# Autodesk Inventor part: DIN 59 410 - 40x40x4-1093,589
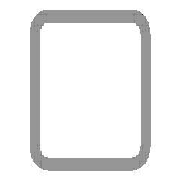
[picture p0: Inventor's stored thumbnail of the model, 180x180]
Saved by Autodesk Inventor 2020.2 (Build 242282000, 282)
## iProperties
Manager: www.cadconsulting.pl
Company: Fabian Stasiak CAD Consulting
IsCustomPart: 1
_CCFamilyMember: 20
_CCFamilyDisplayName: DIN 59410 (Kwadrat) - Rurki stalowe o przekroju kwadratowym formowane na gorąco
_FrameMemberDoc: Frame Member File
_Version: 15.0.0
_GetPNFromCC: 1
Created: 2015-01
Part Number: DIN 59 410 - 40x40x4-1093,589
Material: Stal, miękka
Description: Rurki stalowe o przekroju kwadratowym formowane na gorąco
Document SubType Name: Modellieren
Standard: DIN
Designer: F.Stasiak
Standards Organization: DIN
Language: pl-PL
Size Designation: 40x40x4
Categories: <MemberInstance><Categories><Category DisplayName="Kształtowniki konstrukcyjne" InternalName="089c4875-fa83-4c05-b084-43b9cc11f5ed" Mnemonic="GRDR"><CategoryPar
Stock Number: 40x40x4
Density: 7.85 g/cm^3
Appearance: Częściowo polerowana
Mass: 4423.13 g
Surface Area: 2832.4 cm^2
Volume: 563.456 cm^3
Catalog Web Link: www.expertbooks.pl
G_W: 40,000 mm
G_H: 40,000 mm
+65DF158C-447B-4050-950E-ACB0F4E1A603+CUTDETAIL1: Wytnij
+30AF1056-0509-4B5D-B1E7-E99203BB6F11+CUTDETAIL2: Wytnij
G_L: 1093,589 mm
Author: F.Stasiak
Subject: Zbiór ćwiczeń. Autodesk Inventor 2020. Kurs Professional
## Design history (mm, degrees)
node "Płaszczyzna początkowa"
node "Płaszczyzna końcowa"
sketch "Szkic1"
  geometry: L1 (-12, 20)-(12, 20); L2 (20, 12)-(20, -12); L3 (12, -20)-(-12, -20); L4 (-20, -12)-(-20, 12); L5 (-30.32, 0)-(30.32, 0) reference; L6 (0, -30.32)-(0, 30.32) reference; L7 (-12, 16)-(12, 16); L8 (16, 12)-(16, -12); L9 (12, -16)-(-12, -16); L10 (-16, -12)-(-16, 12); A1 r 8 centre (-12, 12) between (-12, 20) and (-20, 12); A2 r 8 centre (12, 12) between (20, 12) and (12, 20); A3 r 8 centre (12, -12) between (12, -20) and (20, -12); A4 r 8 centre (-12, -12) between (-20, -12) and (-12, -20); A5 r 4 centre (-12, 12) between (-12, 16) and (-16, 12); A6 r 4 centre (12, 12) between (16, 12) and (12, 16); A7 r 4 centre (12, -12) between (12, -16) and (16, -12); A8 r 4 centre (-12, -12) between (-16, -12) and (-12, -16); 3 further points
  constraints: 16 end point, 16 point on circle, 8 centre point, 8 tangent, 6 point on line, 4 parallel, 3 equal radius, 3 perpendicular, 1 horizontal, 7 other
  dimensions: "b" = 40 distance of point (-20, 20) point (20, 20); "msp_r" = 8 radius of A1 (= 2 x ParT); "d8" = 20 distance between parallel lines of L4 L6 (= d9); "d9" = 20 distance between parallel lines of L3 L5 (= 0.5 x b); "d10" = 4 distance between parallel lines of L3 L9 (= ParT)
extrude "Bryła" new body sketch "Szkic1" taper "d4" = 0 deg; stored distance "NLG" = 10
node "Driven Length"
  sketch "Sketch2"
    geometry: L1 (0, 0)-(10, 0) reference
    constraints: 2 end point, 1 horizontal
  workplane "Work Plane3"
  sketch "Sketch3"
    geometry: L1 (-2, 22.426)-(12, 22.426) reference; L2 (-2, 1116.016)-(12, 1116.016) reference
    dimensions: "d14" = 1093.5891 distance between parallel lines of L1 L2 (derived)
node "Płaszczyzna konstrukcyjna4"
feature "Podział1"
node "Płaszczyzna konstrukcyjna5"
feature "Podział2"
body "Solid1"
other parameters: "ParT" = 4, "G_OFFSET_START" = -22.42641 [user parameter; used in 1 equation term], "G_OFFSET_END" = -15.35534 [user parameter; used in 1 equation term], "d11" = 22.42641 (= -G_OFFSET_START), "d12" = 1116.01551 (= G_OFFSET_END + B_L), "G_L" = 1093.5891 (= d14) [user parameter], "B_L" = 1131.37085 [user parameter; used in 1 equation term], "d13" = 90 deg
